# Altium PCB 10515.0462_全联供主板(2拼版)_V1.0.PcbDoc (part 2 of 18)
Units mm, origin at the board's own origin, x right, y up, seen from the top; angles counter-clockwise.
Board outline 282 x 198 mm, 2 copper layers (Top Layer, Bottom Layer); 716 components, 0 nets, 2364 pads, 1800 vias.
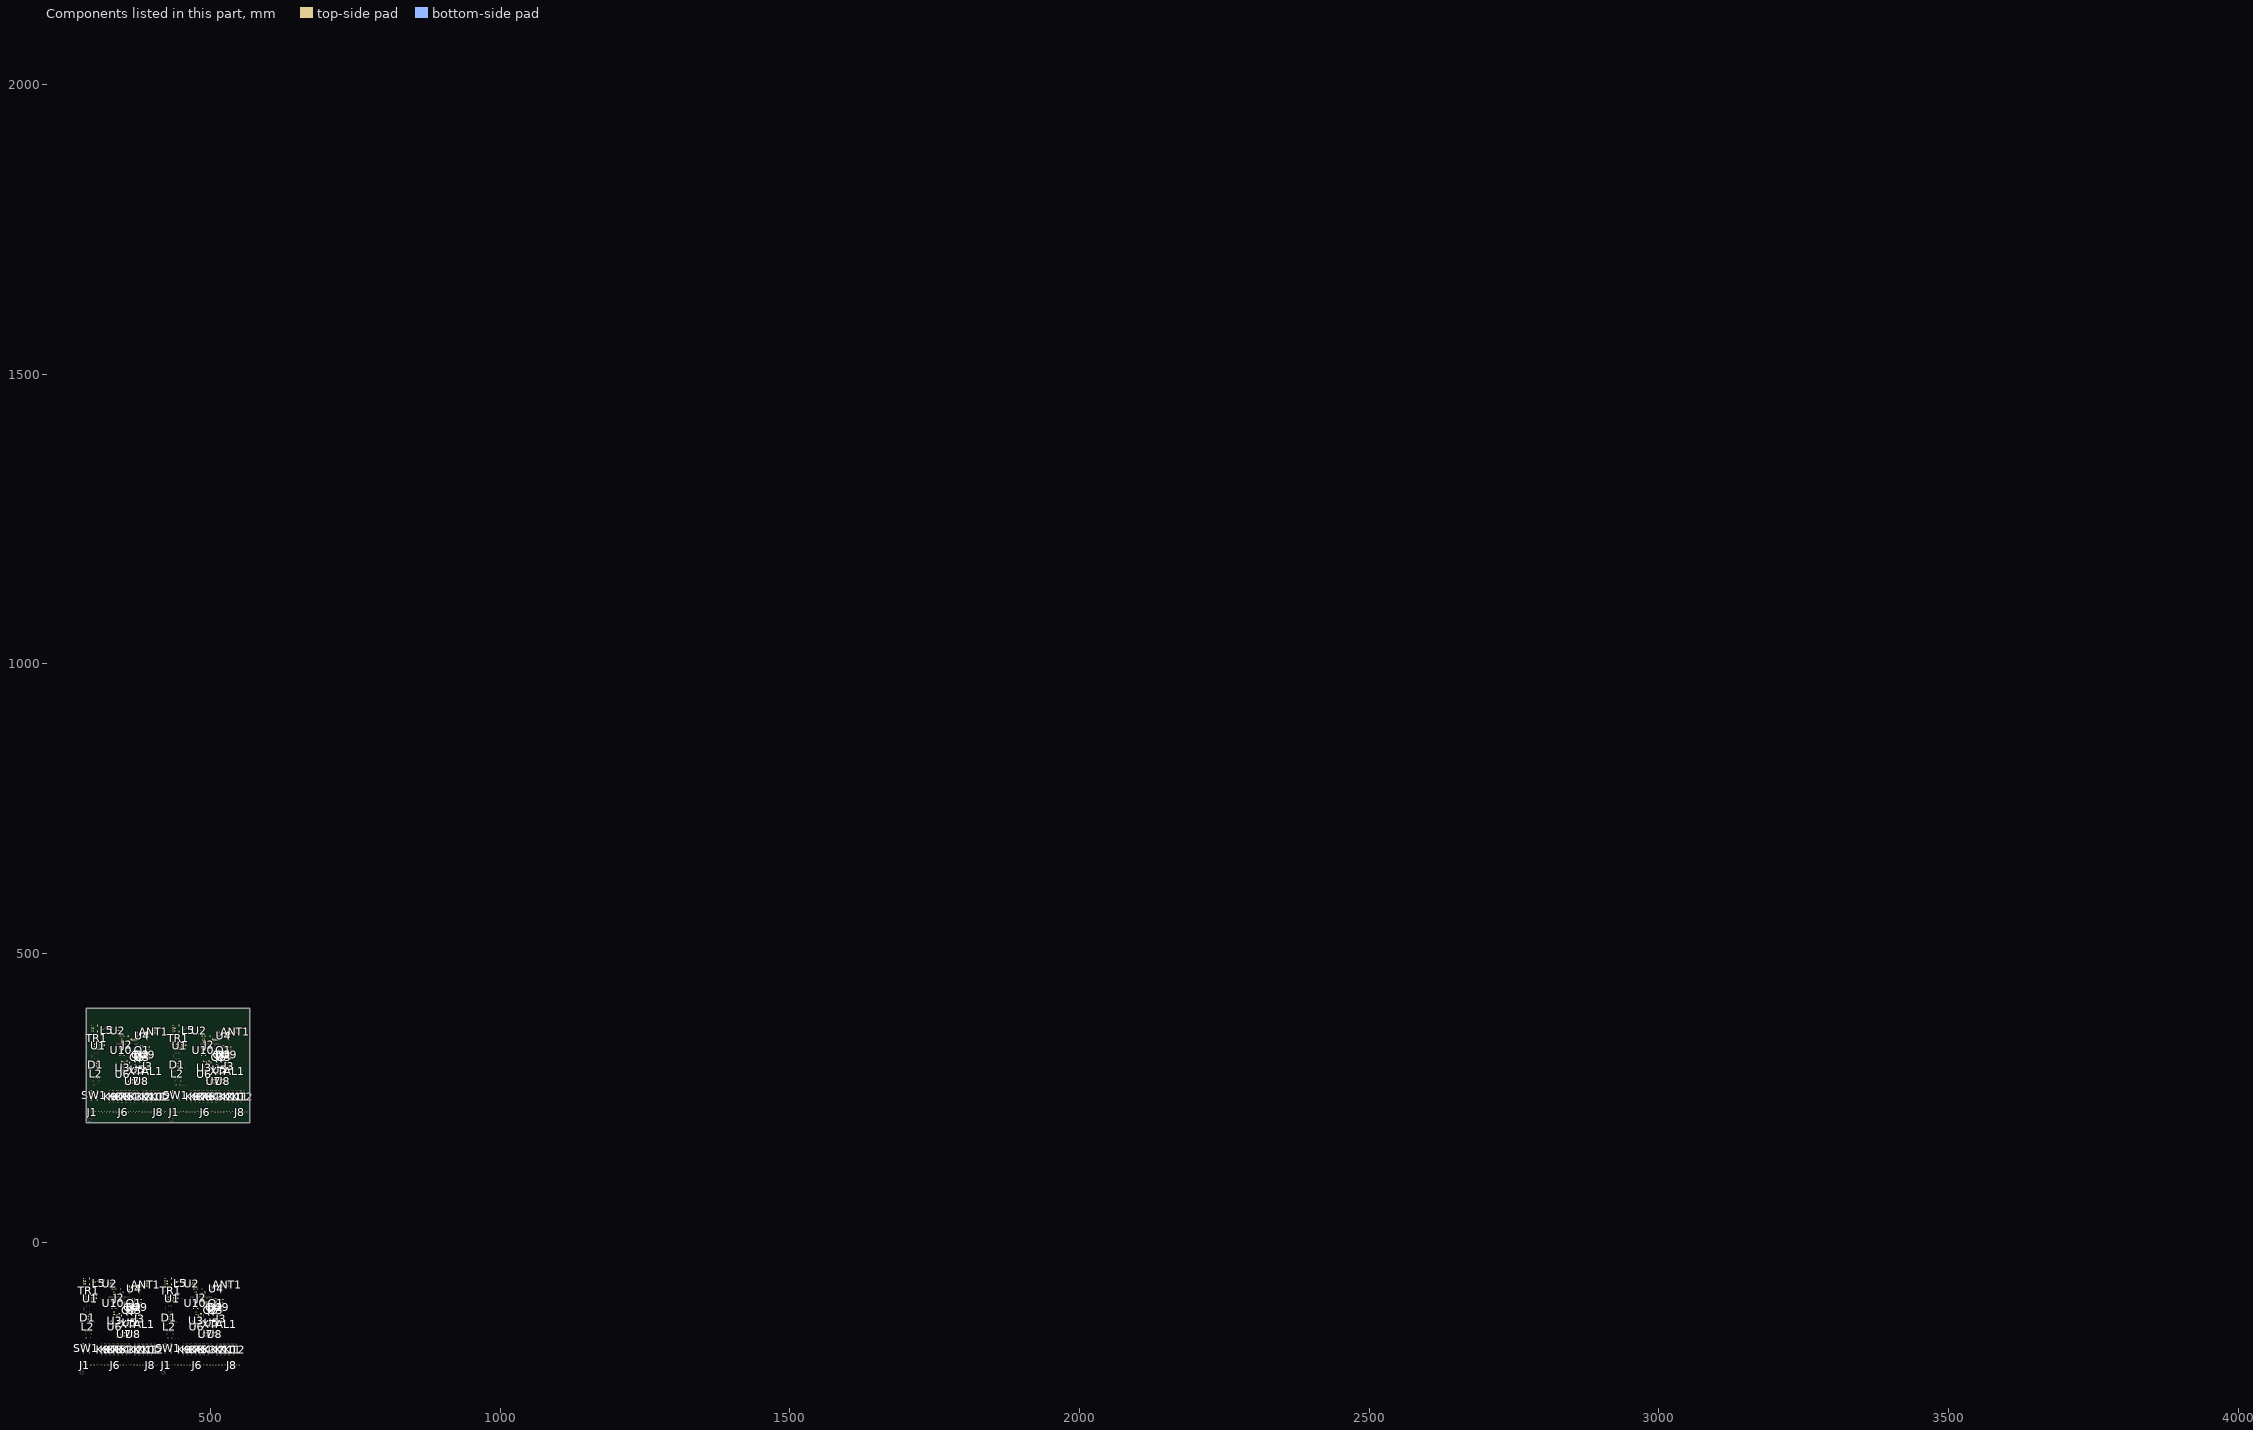
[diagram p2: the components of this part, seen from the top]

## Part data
ANT1 ANT1 ANT1 ANT1: library part OTHER/Antena/SMA座
C1 C1 C1 C1 C2 C2 C2 C2: library part CAP/CAP/SMT/1206C
C3 C3 C3 C3 C4 C4 C4 C4 C5 C5 C5 C5 C6 C6 C6 C6 C7 C7 C7 C7 C8 C8 C8 C8 C9 C9 C9 C9 C10 C10 C10 C10 C11 C11 C11 C11 C12 C12 C12 C12 C13 C13 C13 C13 C14 C14 C14 C14 C15 C15 C15 C15 C16 C16 C16 C16 C17 C17 C17 C17 C18 C18 C18 C18 C19 C19 C19 C19 C20 C20 C20 C20 C21 C21 C21 C21 C22 C22 C22 C22 C23 C23 C23 C23 C24 C24 C24 C24 C25 C25 C25 C25 C26 C26 C26 C26 C27 C27 C27 C27 C28 C28 C28 C28 C29 C29 C29 C29 C30 C30 C30 C30 C31 C31 C31 C31 C32 C32 C32 C32 C35 C35 C35 C35 C36 C36 C36 C36 C37 C37 C37 C37 C40 C40 C40 C40 C44 C44 C44 C44 C45 C45 C45 C45 C46 C46 C46 C46 C48 C48 C48 C48 C49 C49 C49 C49: library part CAP/CAP/SMT/0603C
C34 C34 C34 C34: library part A_Cap_0805
C42 C42 C42 C42 C43 C43 C43 C43: library part CAP/CAP/SMT/0805C
CX1 CX1 CX1 CX1: library part CAP/DIP/0.1uF/275V
CY1 CY1 CY1 CY1 CY2 CY2 CY2 CY2 CY3 CY3 CY3 CY3 CY4 CY4 CY4 CY4: library part CAP/DIP/102M/250V
D1 D1 D1 D1: library part D/BRIDGE/SMT/MB10S, "D_Bridge"
D2 D2 D2 D2: library part D/D/SMT/SS210/DO-214
D3 D3 D3 D3: library part D/D/SMT/1N4007-SOD123
D4 D4 D4 D4: library part D/D/SMT/FFM107/DO-214
D5 D5 D5 D5: library part D/D/SMT/1N4148/SOD-123, "VR=75V T(-65-175)P(0.5W)VF=0.6V"
D6 D6 D6 D6 D9 D9 D9 D9 D10 D10 D10 D10: library part D/TVS/SMT/SMBJ6.5A/DO-214
EC1 EC1 EC1 EC1 EC2 EC2 EC2 EC2: library part CAP/AEC/DIP/6.8uF/400V
EC3 EC3 EC3 EC3 EC8 EC8 EC8 EC8: library part CAP/AEC/DIP/330uF/25V
EC4 EC4 EC4 EC4: library part CAP/AEC/DIP/10uF/50V
EC5 EC5 EC5 EC5: library part CAP/AEC/SMT/220uF/50V
EC6 EC6 EC6 EC6: library part CAP/AEC/SMT/220uF/16V
EC7 EC7 EC7 EC7: library part CAP/AEC/SMT/330uF/6.3V
EC9 EC9 EC9 EC9: library part CAP/TEC/SMT/TAJC476M010RNJ
EC11 EC11 EC11 EC11: library part CAP/AEC/SMT/100uF/25V
J1 J1 J1 J1: library part CON/DIP/1X3PIN/WJ103-5.0MM, "Connector"
J2 J2 J2 J2: "Connector"
J3 J3 J3 J3: library part CON/DIP/1X5PIN_2MM, "Connector"
J6 J6 J6 J6: library part CON/DIP/1X18PIN/WJ103-5.0MM, "Connector"
J8 J8 J8 J8: library part CON/DIP/1X6PIN/WJ103-5.0MM, "Connector"
K1 K1 K1 K1 K2 K2 K2 K2 K3 K3 K3 K3 K4 K4 K4 K4 K5 K5 K5 K5 K6 K6 K6 K6 K7 K7 K7 K7 K8 K8 K8 K8 K9 K9 K9 K9 K10 K10 K10 K10 K11 K11 K11 K11 K12 K12 K12 K12: library part RELAY/GENERAL/DIP/HF46F/012-HS1T
L1 L1 L1 L1: library part L/L/DIP/JYGX68-1.0mH/300mA, "工字电感"
L2 L2 L2 L2: library part L/L/DIP/20mH, "共模电感"
L3 L3 L3 L3: library part L/L/SMT/SWPA3015S150MT, "电感3.0MM*3.0MM*1.5MM"
L4 L4 L4 L4: library part L/BEAD/SMT/0603L
L5 L5 L5 L5: library part L/L/DIP/100uH_共模电感, "共模电感"
LED1 LED1 LED1 LED1: library part D/LED/SMT/BL-HG635A-TRB高亮绿/0805
Q1 Q1 Q1 Q1: library part PNP, "PNP Bipolar Transistor"
Q2 Q2 Q2 Q2 Q3 Q3 Q3 Q3 Q4 Q4 Q4 Q4 Q5 Q5 Q5 Q5: library part BJT/NPN/SMT/SS8050/SOT-23, "Vce25V/Vcb40V/Veb5V/Ic1.5V/Pd300mW"
R1 R1 R1 R1 R2 R2 R2 R2 R3 R3 R3 R3 R4 R4 R4 R4 R6 R6 R6 R6 R45 R45 R45 R45 R48 R48 R48 R48 R56 R56 R56 R56 R58 R58 R58 R58: library part RES/RES/SMT/1206
R5 R5 R5 R5 R13 R13 R13 R13 R14 R14 R14 R14 R15 R15 R15 R15 R16 R16 R16 R16 R17 R17 R17 R17 R18 R18 R18 R18 R19 R19 R19 R19 R20 R20 R20 R20 R21 R21 R21 R21 R22 R22 R22 R22 R23 R23 R23 R23 R24 R24 R24 R24 R25 R25 R25 R25 R26 R26 R26 R26 R27 R27 R27 R27 R28 R28 R28 R28 R29 R29 R29 R29 R30 R30 R30 R30 R31 R31 R31 R31 R32 R32 R32 R32 R33 R33 R33 R33 R34 R34 R34 R34 R35 R35 R35 R35 R36 R36 R36 R36 R37 R37 R37 R37 R38 R38 R38 R38 R39 R39 R39 R39 R40 R40 R40 R40 R69 R69 R69 R69: library part RES/RES/SMT/0603
R7 R7 R7 R7 R8 R8 R8 R8 R9 R9 R9 R9 R10 R10 R10 R10 R11 R11 R11 R11 R12 R12 R12 R12: library part RES/RES/SMT/0805
R41 R41 R41 R41 R42 R42 R42 R42 R43 R43 R43 R43 R44 R44 R44 R44 R46 R46 R46 R46 R47 R47 R47 R47 R49 R49 R49 R49 R50 R50 R50 R50 R51 R51 R51 R51 R52 R52 R52 R52: library part A_Res_0805, "Resistor"
R53 R53 R53 R53 R54 R54 R54 R54 R55 R55 R55 R55 R57 R57 R57 R57 R59 R59 R59 R59 R60 R60 R60 R60 R61 R61 R61 R61 R62 R62 R62 R62: library part Res1, "Resistor"
RF1 RF1 RF1 RF1: library part FUSE/FUSE/DIP/3.15A
RY1 RY1 RY1 RY1: library part RES/RY/DIP/TDK471KD14
SW1 SW1 SW1 SW1: library part SWITCH/POWER/DIP/船型开关
TR1 TR1 TR1 TR1: library part "L/TRANS/DIP/PN8370 24V 0.4A"
U1 U1 U1 U1: library part IC/POWER/SMT/PN8366/SOP-8
U2 U2 U2 U2: library part IC/POWER/SMT/MPS2314/SOT23-8
U3 U3 U3 U3: library part IC/OP/SMT/SGM358YS/SOIC-8, "1MHz 60uA Rail-to-Rail i/o CMOS OP"
U4 U4 U4 U4: library part MODLE/RF/LSD4RF-2F717N30
U5 U5 U5 U5: library part MCU/SMT/STM32F030RCT6/LQFP64
U6 U6 U6 U6: library part IC/FLASH/SMT/M24512-RMN6TP/SO8, "512 Kbit serial I2C bus EEPROM with three Chip Enable lines"
U7 U7 U7 U7 U8 U8 U8 U8: library part IC/DRIVE/SMT/ULN2003ADR/SOIC-16, "High-Voltage, High-Current Darlington Array"
U9 U9 U9 U9: library part MAX487
U10 U10 U10 U10: library part IC/POWER/SMT/SPX1117M3-L3.3TR/SOT-223
XTAL1 XTAL1 XTAL1 XTAL1: library part XTAL/SMT/OSC12MHZ-2

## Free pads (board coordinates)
  round 7 hole 4: 0(277.221,-223.927) 0(290.85,212.668) 0(418.221,-223.927) 0(431.85,212.668)
  round 2 on Top Solder: 0(309.225,-95.784) 0(322.854,340.811) 0(392.791,-158.268) 0(406.42,278.327) 0(450.225,-95.784) 0(463.854,340.811) 0(533.791,-158.268) 0(547.42,278.327)
  round 1 all layers, no hole: 0(309.225,-95.784) 0(322.854,340.811) 0(392.791,-158.268) 0(406.42,278.327) 0(450.225,-95.784) 0(463.854,340.811) 0(533.791,-158.268) 0(547.42,278.327)
  round 2 on Bottom Solder: 0(309.225,-95.784) 0(322.854,340.811) 0(392.791,-158.268) 0(406.42,278.327) 0(450.225,-95.784) 0(463.854,340.811) 0(533.791,-158.268) 0(547.42,278.327)

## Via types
v1: diameter 0.7, hole 0.4, Top Layer to Bottom Layer, tented both sides, 1800 vias

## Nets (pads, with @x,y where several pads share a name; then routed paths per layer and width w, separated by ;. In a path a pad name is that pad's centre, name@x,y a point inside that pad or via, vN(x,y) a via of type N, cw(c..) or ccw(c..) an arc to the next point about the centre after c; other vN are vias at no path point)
pads on no net: +3.3V.1 ANT1.1 ANT1.2 ANT1.3 ANT1.4 ANT1.5 C1.1 C1.2 C2.1 C2.2 C3.1 C3.2 C4.1 C4.2 C5.1 C5.2 C6.1 C6.2 C7.1 C7.2 C8.1 C8.2 C9.1 C9.2 C10.1 C10.2 C11.1 C11.2 C12.1 C12.2 C13.1 C13.2 C14.1 C14.2 C15.1 C15.2 C16.1 C16.2 C17.1 C17.2 C18.1 C18.2 C19.1 C19.2 C20.1 C20.2 C21.1 C21.2 C22.1 C22.2 C23.1 C23.2 C24.1 C24.2 C25.1 C25.2 C26.1 C26.2 C27.1 C27.2 C28.1 C28.2 C29.1 C29.2 C30.1 C30.2 C31.1 C31.2 C32.1 C32.2 C34.1 C34.2 C35.1 C35.2 C36.1 C36.2 C37.1 C37.2 C40.1 C40.2 C42.1 C42.2 C43.1 C43.2 C44.1 C44.2 C45.1 C45.2 C46.1 C46.2 C48.1 C48.2 C49.1 C49.2 CX1.1 CX1.2 CY1.1 CY1.2 CY2.1 CY2.2 CY3.1 CY3.2 CY4.1 CY4.2 D1.1 D1.2 D1.3 D1.4 D2.1 D2.2 D3.1 D3.2 D4.1 D4.2 D5.1 D5.2 D6.1 D6.2 D9.1 D9.2 D10.1 D10.2 EC1.1 EC1.2 EC2.1 EC2.2 EC3.1 EC3.2 EC4.1 EC4.2 EC5.1 EC5.2 EC6.1 EC6.2 EC7.1 EC7.2 EC8.1 EC8.2 EC9.1 EC9.2 EC11.1 EC11.2 GND1.1 J1.1 J1.2 J1.3 J2.1 J2.2 J2.3 J2.4 J2.5 J2.6 J2.7 J2.8 J2.9 J2.10 J2.11 J2.12 J2.13 J2.14 J2.15 J2.16 J2.17 J2.18 J2.19 J2.20 J2.21 J2.22 J2.23 J2.24 J2.25 J2.26 J2.27 J2.28 J2.29 J2.30 J3.1 J3.2 J3.3 J3.4 J3.5 J6.1 J6.2 J6.3 J6.4 J6.5 J6.6 J6.7 J6.8 J6.9 J6.10 J6.11 J6.12 J6.13 J6.14 J6.15 J6.16 J6.17 J6.18 J8.1 J8.2 J8.3 J8.4 J8.5 J8.6 K1.1 K1.2 K1.3 K1.4 K2.1 K2.2 K2.3 K2.4 K3.1 K3.2 K3.3 K3.4 K4.1 K4.2 K4.3 K4.4 K5.1 K5.2 K5.3 K5.4 K6.1 K6.2 K6.3 K6.4 K7.1 K7.2 K7.3 K7.4 K8.1 K8.2 K8.3 K8.4 K9.1 K9.2 K9.3 K9.4 K10.1 K10.2 K10.3 K10.4 K11.1 K11.2 K11.3 K11.4 K12.1 K12.2 K12.3 K12.4 L1.1 L1.2 L2.1 L2.2 L2.3 L2.4 L3.1 L3.2 L4.1 L4.2 L5.1 L5.2 L5.3 L5.4 LED1.1 LED1.2 Q1.1 Q1.2 Q1.3 Q2.1 Q2.2 Q2.3 Q3.1 Q3.2 Q3.3 Q4.1 Q4.2 Q4.3 Q5.1 Q5.2 Q5.3 R1.1 R1.2 R2.1 R2.2 R3.1 R3.2 R4.1 R4.2 R5.1 R5.2 R6.1 R6.2 R7.1 R7.2 R8.1 R8.2 R9.1 R9.2 R10.1 R10.2 R11.1 R11.2 R12.1 R12.2 R13.1 R13.2 R14.1 R14.2 R15.1 R15.2 R16.1 R16.2 R17.1 R17.2 R18.1 R18.2 R19.1 R19.2 R20.1 R20.2 R21.1 R21.2 R22.1 R22.2 R23.1 R23.2 R24.1 R24.2 R25.1 R25.2 R26.1 R26.2 R27.1 R27.2 R28.1 R28.2 R29.1 R29.2 R30.1 R30.2 R31.1 R31.2 R32.1 R32.2 R33.1 R33.2 R34.1 R34.2 R35.1 R35.2 R36.1 R36.2 R37.1 R37.2 R38.1 R38.2 R39.1 R39.2 R40.1 R40.2 R41.1 R41.2 R42.1 R42.2 R43.1 R43.2 R44.1 R44.2 R45.1 R45.2 R46.1 R46.2 R47.1 R47.2 R48.1 R48.2 R49.1 R49.2 R50.1 R50.2 R51.1 R51.2 R52.1 R52.2 R53.1 R53.2 R54.1 R54.2 R55.1 R55.2 R56.1 R56.2 R57.1 R57.2 R58.1 R58.2 R59.1 R59.2 R60.1 R60.2 R61.1 R61.2 R62.1 R62.2 R69.1 R69.2 RF1.1 RF1.2 RXD1.1 RY1.1 RY1.2 SW1. SW1.2 SW1.4 T1.1 TR1.1 TR1.3 TR1.4 TR1.5 TR1.8 TR1.10 TXD1.1 U1.1 U1.2 U1.3 U1.4 U1.5 U1.6 U1.7 U2.1 U2.2 U2.3 U2.4 U2.5 U2.6 U2.7 U2.8 U3.1 U3.2 U3.3 U3.4 U3.5 U3.6 U3.7 U3.8 U4.1 U4.2 U4.3 U4.4 U4.5 U4.6 U4.7 U4.8 U4.9 U4.10 U4.11 U4.12 U4.13 U4.14 U5.1 U5.2 U5.3 U5.4 U5.5 U5.6 U5.7 U5.8 U5.9 U5.10 U5.11 U5.12 U5.13 U5.14 U5.15 U5.16 U5.17 U5.18 U5.19 U5.20 U5.21 U5.22 U5.23 U5.24 U5.25 U5.26 U5.27 U5.28 U5.29 U5.30 U5.31 U5.32 U5.33 U5.34 U5.35 U5.36 U5.37 U5.38 U5.39 U5.40 U5.41 U5.42 U5.43 U5.44 U5.45 U5.46 U5.47 U5.48 U5.49 U5.50 U5.51 U5.52 U5.53 U5.54 U5.55 U5.56 U5.57 U5.58 U5.59 U5.60 U5.61 U5.62 U5.63 U5.64 U6.1 U6.2 U6.3 U6.4 U6.5 U6.6 U6.7 U6.8 U7.1 U7.2 U7.3 U7.4 U7.5 U7.6 U7.7 U7.8 U7.9 U7.10 U7.11 U7.12 U7.13 U7.14 U7.15 U7.16 U8.1 U8.2 U8.3 U8.4 U8.5 U8.6 U8.7 U8.8 U8.9 U8.10 U8.11 U8.12 U8.13 U8.14 U8.15 U8.16 U9.1 U9.2 U9.3 U9.4 U9.5 U9.6 U9.7 U9.8 U10.1 U10.2 U10.3 XTAL1.1 XTAL1.2 XTAL1.3 XTAL1.4
copper on no net: | length 38525.5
